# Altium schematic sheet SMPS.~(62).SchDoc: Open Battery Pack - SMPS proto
size A3; Date: 26/03/2019; Author: Morgane Vallée - Samuel Lesueur; Revision: 1.0; SheetNumber: 1; SheetTotal: 1
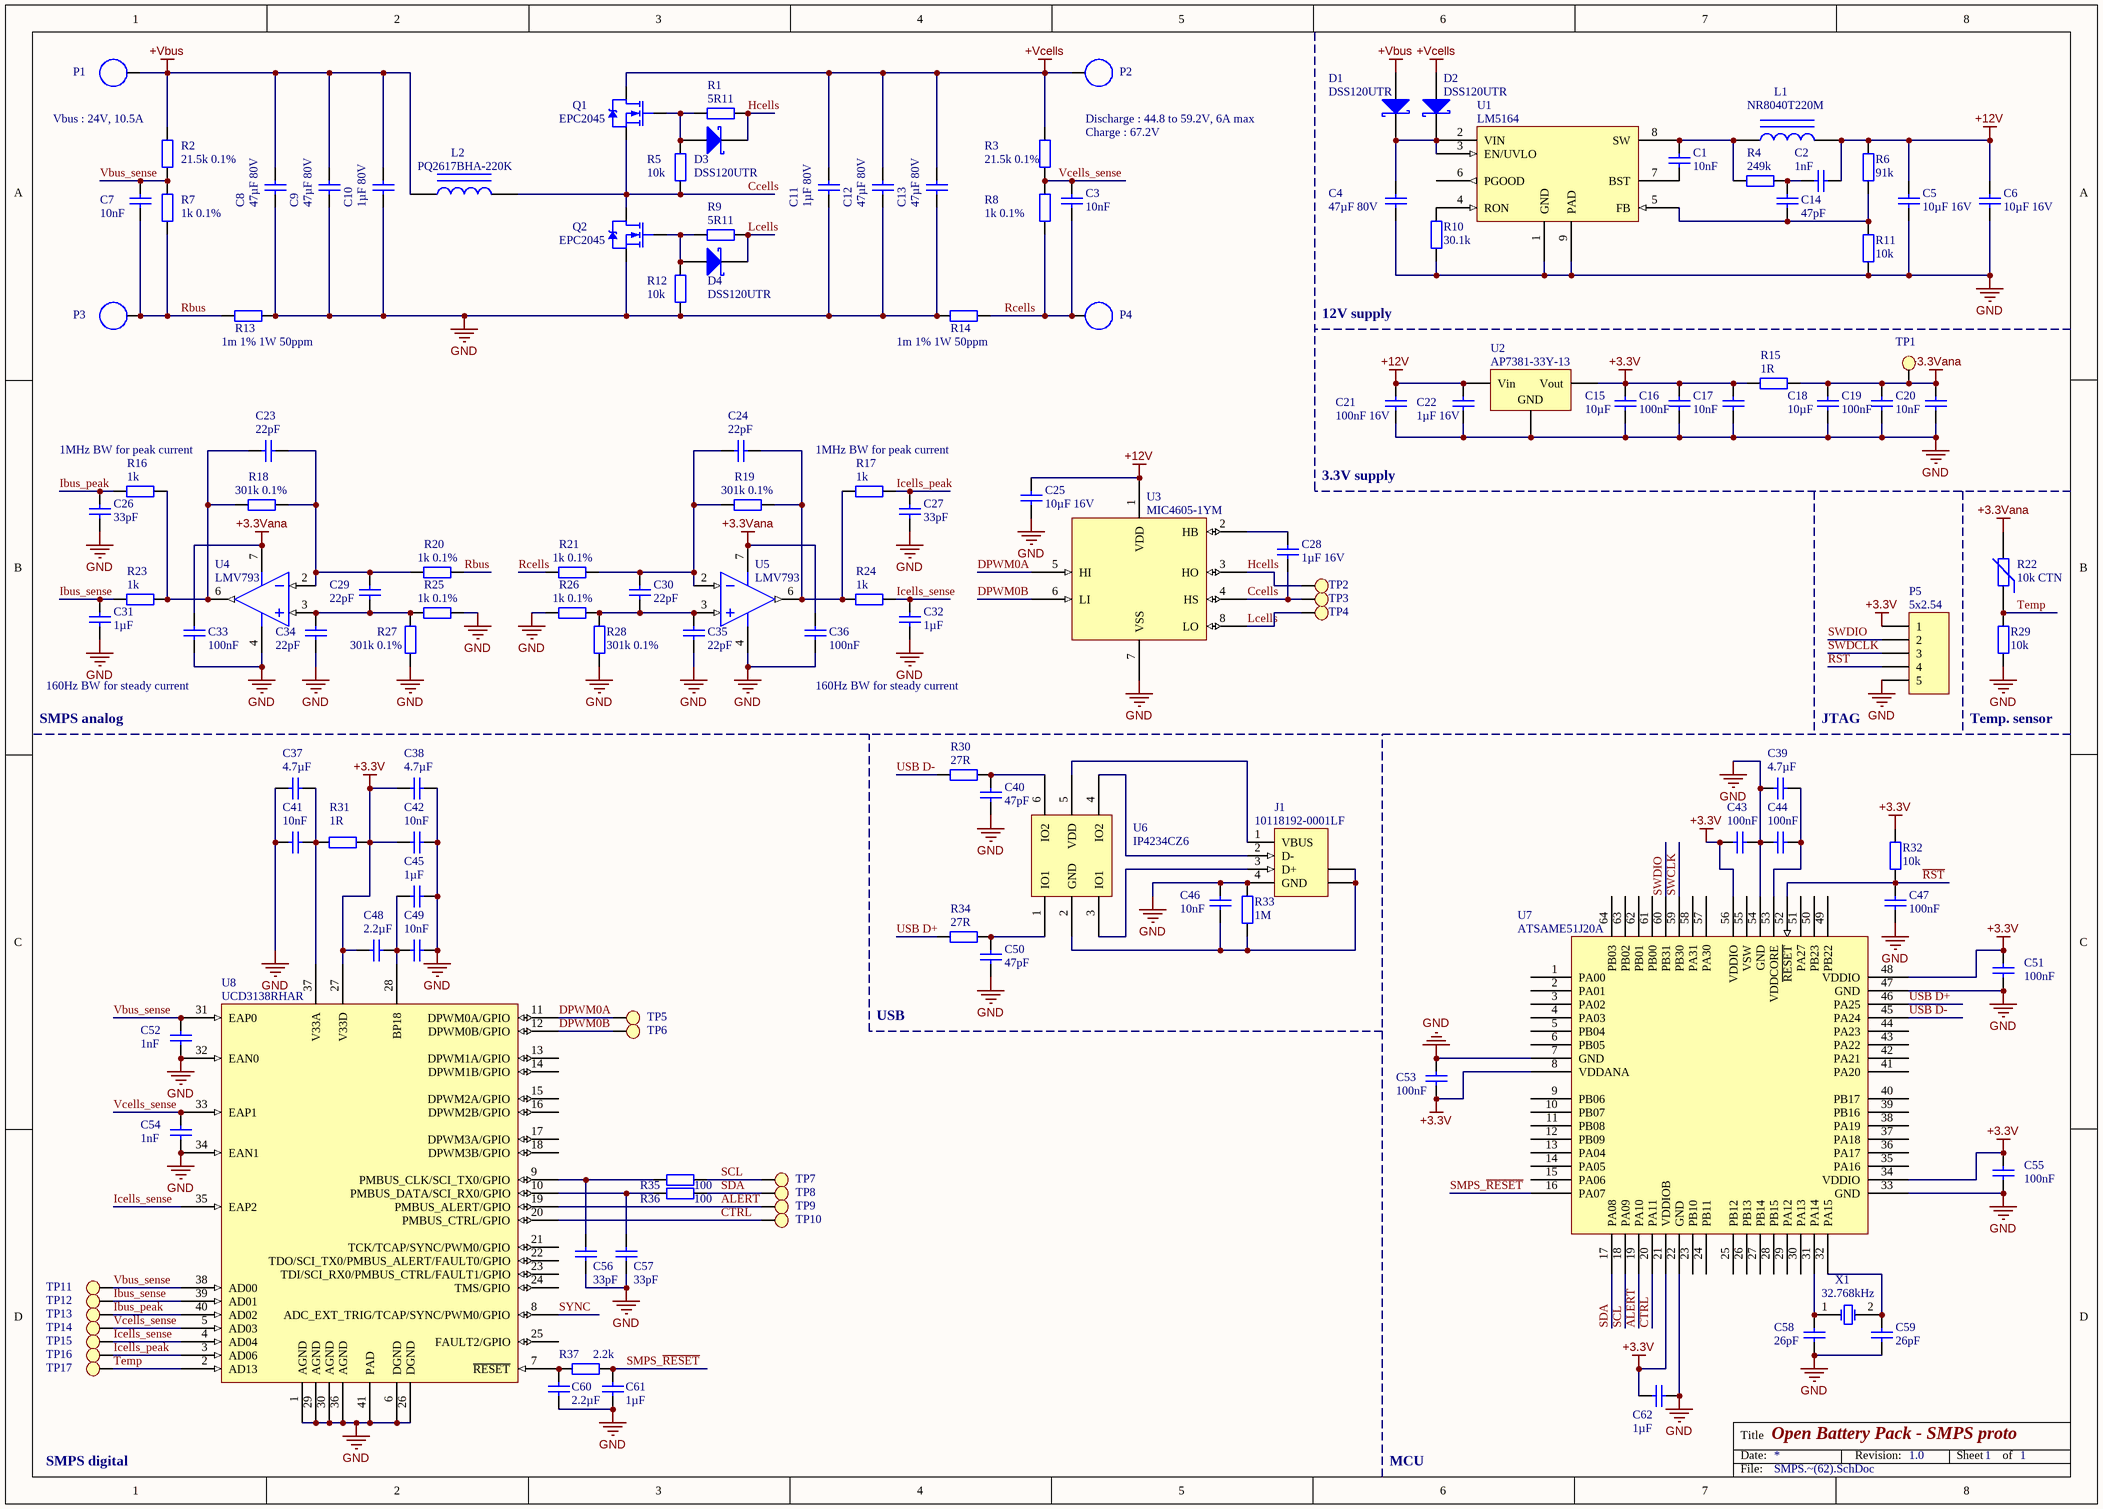
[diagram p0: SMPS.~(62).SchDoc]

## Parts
C1  10nF  [C0603]
C2  1nF  [C0603]
C3  10nF  [C0603]
C4  47µF 80V  [CAP ALUM 10.3MM]
C5  10µF 16V  [C0805]
C6  10µF 16V  [C0805]
C7  10nF  [C0603]
C8  47µF 80V  [CAP ALUM 10.3MM]
C9  47µF 80V  [CAP ALUM 10.3MM]
C10  1µF 80V  [C1206]
C11  1µF 80V  [C1206]
C12  47µF 80V  [CAP ALUM 10.3MM]
C13  47µF 80V  [CAP ALUM 10.3MM]
C14  47pF  [C0603]
C15  10µF  [C0603]
C16  100nF  [C0603]
C17  10nF  [C0603]
C18  10µF  [C0603]
C19  100nF  [C0603]
C20  10nF  [C0603]
C21  100nF 16V  [C0603]
C22  1µF 16V  [C0805]
C23  22pF  [C0603]
C24  22pF  [C0603]
C25  10µF 16V  [C0805]
C26  33pF  [C0603]
C27  33pF  [C0603]
C28  1µF 16V  [C0603]
C29  22pF  [C0603]
C30  22pF  [C0603]
C31  1µF  [C0603]
C32  1µF  [C0603]
C33  100nF  [C0603]
C34  22pF  [C0603]
C35  22pF  [C0603]
C36  100nF  [C0603]
C37  4.7µF  [C0603]
C38  4.7µF  [C0603]
C39  4.7µF  [C0603]
C40  47pF  [C0603]
C41  10nF  [C0603]
C42  10nF  [C0603]
C43  100nF  [C0603]
C44  100nF  [C0603]
C45  1µF  [C0603]
C46  10nF  [C0603]
C47  100nF  [C0603]
C48  2.2µF  [C0603]
C49  10nF  [C0603]
C50  47pF  [C0603]
C51  100nF  [C0603]
C52  1nF  [C0603]
C53  100nF  [C0603]
C54  1nF  [C0603]
C55  100nF  [C0603]
C56  33pF  [C0603]
C57  33pF  [C0603]
C58  26pF  [C0603]
C59  26pF  [C0603]
C60  2.2µF  [C0603]
C61  1µF  [C0603]
C62  1µF  [C0603]
D1  DSS120UTR  [SOD123F]
D2  DSS120UTR  [SOD123F]
D3  DSS120UTR  [SOD123F]
D4  DSS120UTR  [SOD123F]
J1  10118192-0001LF  [FCI USB 10118193-0001LF]
L1  NR8040T220M  [SELF_SMD_8x8]
L2  PQ2617BHA-220K  [SELF_SMD_PQ2617]
P1  PTH  [HOLE_4]  (value not drawn)
P2  PTH  [HOLE_4]  (value not drawn)
P3  PTH  [HOLE_4]  (value not drawn)
P4  PTH  [HOLE_4]  (value not drawn)
P5  5x2.54  [SAMTEC SSW-105-03-T-S]
Q1  EPC2045  [EPC2045]
Q2  EPC2045  [EPC2045]
R1  5R11  [R0603]
R2  21.5k 0.1%  [R0603]
R3  21.5k 0.1%  [R0603]
R4  249k  [R0603]
R5  10k  [R0603]
R6  91k  [R0603]
R7  1k 0.1%  [R0603]
R8  1k 0.1%  [R0603]
R9  5R11  [R0603]
R10  30.1k  [R0603]
R11  10k  [R0603]
R12  10k  [R0603]
R13  1m 1% 1W 50ppm  [R1206]
R14  1m 1% 1W 50ppm  [R1206]
R15  1R  [R0603]
R16  1k  [R0603]
R17  1k  [R0603]
R18  301k 0.1%  [R0603]
R19  301k 0.1%  [R0603]
R20  1k 0.1%  [R0603]
R21  1k 0.1%  [R0603]
R22  10k CTN  [NTC 0402/1005]
R23  1k  [R0603]
R24  1k  [R0603]
R25  1k 0.1%  [R0603]
R26  1k 0.1%  [R0603]
R27  301k 0.1%  [R0603]
R28  301k 0.1%  [R0603]
R29  10k  [R0603]
R30  27R  [R0603]
R31  1R  [R0603]
R32  10k  [R0603]
R33  1M  [R0603]
R34  27R  [R0603]
R35  100  [R0603]
R36  100  [R0603]
R37  2.2k  [R0603]
TP1  Test Point  [Test Point]  (value not drawn)
TP2  Test Point  [Test Point]  (value not drawn)
TP3  Test Point  [Test Point]  (value not drawn)
TP4  Test Point  [Test Point]  (value not drawn)
TP5  Test Point  [Test Point]  (value not drawn)
TP6  Test Point  [Test Point]  (value not drawn)
TP7  Test Point  [Test Point]  (value not drawn)
TP8  Test Point  [Test Point]  (value not drawn)
TP9  Test Point  [Test Point]  (value not drawn)
TP10  Test Point  [Test Point]  (value not drawn)
TP11  Test Point  [Test Point]  (value not drawn)
TP12  Test Point  [Test Point]  (value not drawn)
TP13  Test Point  [Test Point]  (value not drawn)
TP14  Test Point  [Test Point]  (value not drawn)
TP15  Test Point  [Test Point]  (value not drawn)
TP16  Test Point  [Test Point]  (value not drawn)
TP17  Test Point  [Test Point]  (value not drawn)
U1  LM5164  [R-PDSO-G8]
U2  AP7381-33Y-13  [ON SEMI SOT-89 H]
U3  MIC4605-1YM  [SOIC-8]
U4  LMV793  [TI SOT-23-5 DBV]
U5  LMV793  [TI SOT-23-5 DBV]
U6  IP4234CZ6  [VISHAY TSOP-6 MO-193C]
U7  ATSAME51J20A  [TQFP-64N]
U8  UCD3138RHAR  [S-PVQFN-N40]
X1  32.768kHz  [ABRACON ABS07]

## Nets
+3.3V: C15.1 C16.1 C17.1 C38.1 C42.1 C43.2 C48.2 C51.2 C53.1 C55.2 C62.2 P5.1 R15.2 R31.1 R32.2 U2.3(Vout) U7.8(VDDANA) U7.21(VDDIOB) U7.34(VDDIO) U7.48(VDDIO) U7.56(VDDIO) U8.27(V33D)
+3.3Vana: C18.1 C19.1 C20.1 C33.1 C36.1 R15.1 R22.2 TP1.1 U4.7(V+) U5.7(V+)
+12V: C2.2 C5.1 C6.1 C21.1 C22.1 C25.2 L1.2 R6.1 U2.1(Vin) U3.1(VDD)
+Vbus: C8.2 C9.2 C10.2 D1.1(A) L2.1 P1.1 R2.1
+Vcells: C11.2 C12.2 C13.2 D2.1(A) P2.1 Q1.3(D) R3.1
GND: C4.1 C5.2 C6.2 C8.1 C9.1 C10.1 C11.1 C12.1 C13.1 C15.2 C16.2 C17.2 C18.2 C19.2 C20.2 C21.2 C22.2 C25.1 C26.1 C27.1 C31.1 C32.1 C33.2 C34.1 C35.1 C36.2 C37.1 C38.2 C39.2 C40.1 C41.1 C42.2 C43.1 C44.2 C45.1 C46.2 C47.1 C49.1 C50.1 C51.1 C52.2 C53.2 C54.2 C55.1 C56.2 C57.2 C58.1 C59.1 C60.2 C61.2 C62.1 J1.4(GND) P5.5 Q2.2(S) R10.2 R11.2 R12.2 R13.1 R14.2 R25.1 R26.2 R27.2 R28.2 R29.2 R33.1 U1.1(GND) U1.9(PAD) U2.2(GND) U3.7(VSS) U4.4(V-) U5.4(V-) U7.7(GND) U7.22(GND) U7.33(GND) U7.47(GND) U7.54(GND) U8.1(AGND) U8.6(DGND) U8.26(DGND) U8.29(AGND) U8.30(AGND) U8.32(EAN0) U8.34(EAN1) U8.36(AGND) U8.41(PAD)
ALERT: TP9.1 U7.19(PA10) U8.19(PMBUS_ALERT/GPIO)
Ccells: C28.1 L2.2 Q1.2(S) Q2.3(D) R5.2 TP3.1 U3.4(HS)
CTRL: TP10.1 U7.20(PA11) U8.20(PMBUS_CTRL/GPIO)
DPWM0A: TP5.1 U3.5(HI) U8.11(DPWM0A/GPIO)
DPWM0B: TP6.1 U3.6(LI) U8.12(DPWM0B/GPIO)
Hcells: D3.2(K) R1.1 TP2.1 U3.3(HO)
Ibus_peak: C26.2 R16.2 TP13.1 U8.40(AD02)
Ibus_sense: C31.2 R23.2 TP12.1 U8.39(AD01)
Icells_peak: C27.2 R17.1 TP16.1 U8.3(AD06)
Icells_sense: C32.2 R24.1 TP15.1 U8.4(AD04) U8.35(EAP2)
Lcells: D4.2(K) R9.1 TP4.1 U3.8(LO)
~{RST}: C47.2 P5.4 R32.1 U7.52(~{RESET})
Rbus: C7.1 P3.1 R7.2 R13.2 R20.1
Rcells: C3.1 P4.1 R8.2 R14.1 R21.2
SCL: R35.2 TP7.1 U7.18(PA09)
SDA: R36.2 TP8.1 U7.17(PA08)
SMPS_~{RESET}: C61.1 R37.2 U7.16(PA07)
SWCLK: U7.59(PB30)
SWDCLK: P5.3
SWDIO: P5.2 U7.60(PB31)
SYNC: U8.8(ADC_EXT_TRIG/TCAP/SYNC/PWM0/GPIO)
Temp: R22.1 R29.1 TP17.1 U8.2(AD13)
USB D+: R34.1 U7.46(PA25)
USB D-: R30.1 U7.45(PA24)
Vbus_sense: C7.2 C52.1 R2.2 R7.1 TP11.1 U8.31(EAP0) U8.38(AD00)
Vcells_sense: C3.2 C54.1 R3.2 R8.1 TP14.1 U8.5(AD03) U8.33(EAP1)
NetC1_1: C1.1 L1.1 R4.1 U1.8(SW)
NetC1_2: C1.2 U1.7(BST)
NetC2_1: C2.1 C14.2 R4.2
NetC4_2: C4.2 D1.2(K) D2.2(K) U1.2(VIN) U1.3(EN/UVLO)
NetC14_1: C14.1 R6.2 R11.1 U1.5(FB)
NetC23_1: C23.1 R16.1 R18.2 R23.1 U4.6(OUT)
NetC23_2: C23.2 C29.2 R18.1 R20.2 U4.2(IN-)
NetC24_1: C24.1 C30.2 R19.2 R21.1 U5.2(IN-)
NetC24_2: C24.2 R17.2 R19.1 R24.2 U5.6(OUT)
NetC28_2: C28.2 U3.2(HB)
NetC29_1: C29.1 C34.2 R25.2 R27.1 U4.3(IN+)
NetC30_1: C30.1 C35.2 R26.1 R28.1 U5.3(IN+)
NetC37_2: C37.2 C41.2 R31.2 U8.37(V33A)
NetC39_1: C39.1 C44.1 U7.53(VDDCORE)
NetC40_2: C40.2 R30.2 U6.6(IO2)
NetC45_2: C45.2 C48.1 C49.2 U8.28(BP18)
NetC46_1: C46.1 J1.5(SHLD) J1.6(SHLD) R33.2 U6.2(GND)
NetC50_2: C50.2 R34.2 U6.1(IO1)
NetC56_1: C56.1 R35.1 U8.9(PMBUS_CLK/SCI_TX0/GPIO)
NetC57_1: C57.1 R36.1 U8.10(PMBUS_DATA/SCI_RX0/GPIO)
NetC58_2: C58.2 U7.31(PA14) X1.1(OSC1)
NetC59_2: C59.2 U7.32(PA15) X1.2(OSC2)
NetC60_1: C60.1 R37.1 U8.7(~{RESET})
NetD3_1: D3.1(A) Q1.1(G) R1.2 R5.1
NetD4_1: D4.1(A) Q2.1(G) R9.2 R12.1
NetJ1_1: J1.1(VBUS) U6.5(VDD)
NetJ1_2: J1.2(D-) U6.4(IO2)
NetJ1_3: J1.3(D+) U6.3(IO1)
NetR10_1: R10.1 U1.4(RON)

Not connected (* = marked no-connect by the designer): U1 6(PGOOD); U7 1(PA00) 2(PA01) 3(PA02) 4(PA03) 5(PB04) 6(PB05) 9(PB06) 10(PB07) 11(PB08) 12(PB09) 13(PA04) 14(PA05) 15(PA06) 23(PB10) 24(PB11) 25(PB12) 26(PB13) 27(PB14) 28(PB15) 29(PA12) 30(PA13) 35(PA16) 36(PA17) 37(PA18) 38(PA19) 39(PB16) 40(PB17) 41(PA20) 42(PA21) 43(PA22) 44(PA23) 49(PB22) 50(PB23) 51(PA27) 55(VSW) 57(PA30) 58(PA31) 61(PB00) 62(PB01) 63(PB02) 64(PB03); U8 13(DPWM1A/GPIO) 14(DPWM1B/GPIO) 15(DPWM2A/GPIO) 16(DPWM2B/GPIO) 17(DPWM3A/GPIO) 18(DPWM3B/GPIO) 21(TCK/TCAP/SYNC/PWM0/GPIO) 22(TDO/SCI_TX0/PMBUS_ALERT/FAULT0/GPIO) 23(TDI/SCI_RX0/PMBUS_CTRL/FAULT1/GPIO) 24(TMS/GPIO) 25(FAULT2/GPIO)

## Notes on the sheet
- (near R2) Vbus : 24V, 10.5A
- Discharge : 44.8 to 59.2V, 6A max
- Charge : 67.2V
- 12V supply
- 1MHz BW for peak current
- 3.3V supply
- SMPS analog
- 160Hz BW for steady current
- JTAG
- Temp. sensor
- USB
- SMPS digital
- MCU

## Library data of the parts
C1-C62 = Cap: Capacitor
D1-D4 = D Schottky: Schottky Diode; pin to pad: 1>1+3
J1 = 1-353576-1: USB 1.1, Right Angle, SMT, A Type, Receptacle, 4 Position, White; pin to pad: 4>5 5>S 6>S
L1 L2 = Inductor Iron: Magnetic-Core Inductor
P1-P4 = PTH: Plated Trough Hole for screew
P5 = Header 5: Header, 5-Pin
Q1 Q2 = MOSFET_N: pin to pad: 2>2+3+7+8+9+13+14+15 3>4+5+6+10+11+12
R1-R21 R23-R37 = Res2: Resistor
R22 = Res Varistor: Varistor (Voltage-Sensitive Resistor)
U1 = LM5164: 100-V Input, 1-A synchronous buck DC/DC converter with ultra-low IQ
U2 = Volt Reg: Voltage Regulator; pin to pad: 1>8 2>2+3+6+7 3>1
U3 = MIC4605-1YM: 85V Half-Bridge MOSFET Driver with Adaptive Dead Time  and Shoot-Through Protection
U4 U5 = AOP - 1: pin to pad: 2>4 4>2 6>1 7>5
U6 = IP4234CZ6: Single USB 2.0 ESD protection to IEC 61000-4-2 level 4
U8 = UCD3138RHAR: Highly Integrated Digital Controller for Isolated Power with 3 Feedback Loops and 8 DPWM Outputs, 40pins
X1 = XTAL: Crystal Oscillator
